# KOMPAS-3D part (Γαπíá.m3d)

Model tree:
1. Эскиз:1
2. Операция выдавливания:1
     Расстояние 1 = 38; Расстояние 2 = 38
3. Эскиз:2
4. Операция выдавливания:2
     Расстояние 1 = 5; Расстояние 2 = 38
5. Эскиз:3
6. Операция выдавливания:3
     Расстояние 1 = 1; Расстояние 2 = 38
7. Эскиз:4
8. Операция выдавливания:4
     Расстояние 1 = 1; Расстояние 2 = 38
9. Эскиз:5
10. Операция выдавливания:5
     Расстояние 1 = 0.1; Расстояние 2 = 38
11. Эскиз:6
12. Операция выдавливания:6
     Расстояние 1 = 1; Расстояние 2 = 38
13. Эскиз:7
14. Операция выдавливания:7
     Расстояние 1 = 0.1; Расстояние 2 = 38
15. Эскиз:8
16. Операция выдавливания:8
     Расстояние 1 = 1; Расстояние 2 = 38
17. Эскиз:9
18. Операция выдавливания:9
     Расстояние 1 = 0.5; Расстояние 2 = 38
19. Скругление:1
     Радиус = 1
20. Скругление:3
     Радиус = 0.2
21. Эскиз:10
22. Операция выдавливания:10
     Расстояние 1 = 6; Расстояние 2 = 38
23. Эскиз:12
24. Вырезать элемент выдавливания:1
     Расстояние 1 = 73
25. Эскиз:13
26. Операция выдавливания:12
     Расстояние 1 = 11; Расстояние 2 = 38
27. Эскиз:14
28. Вырезать элемент выдавливания:2
     Расстояние 1 = 71
29. Эскиз:15
30. Вырезать элемент выдавливания:3
     Расстояние 1 = 71
31. Скругление:4
     Радиус = 0.2
32. Скругление:5
     Радиус = 0.2
33. Скругление:6
     Радиус = 0.2
34. Скругление:7
     Радиус = 0.2
35. Скругление:8
     Радиус = 0.2

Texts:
  Сплав АЛ8  ГОСТ 1583-93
